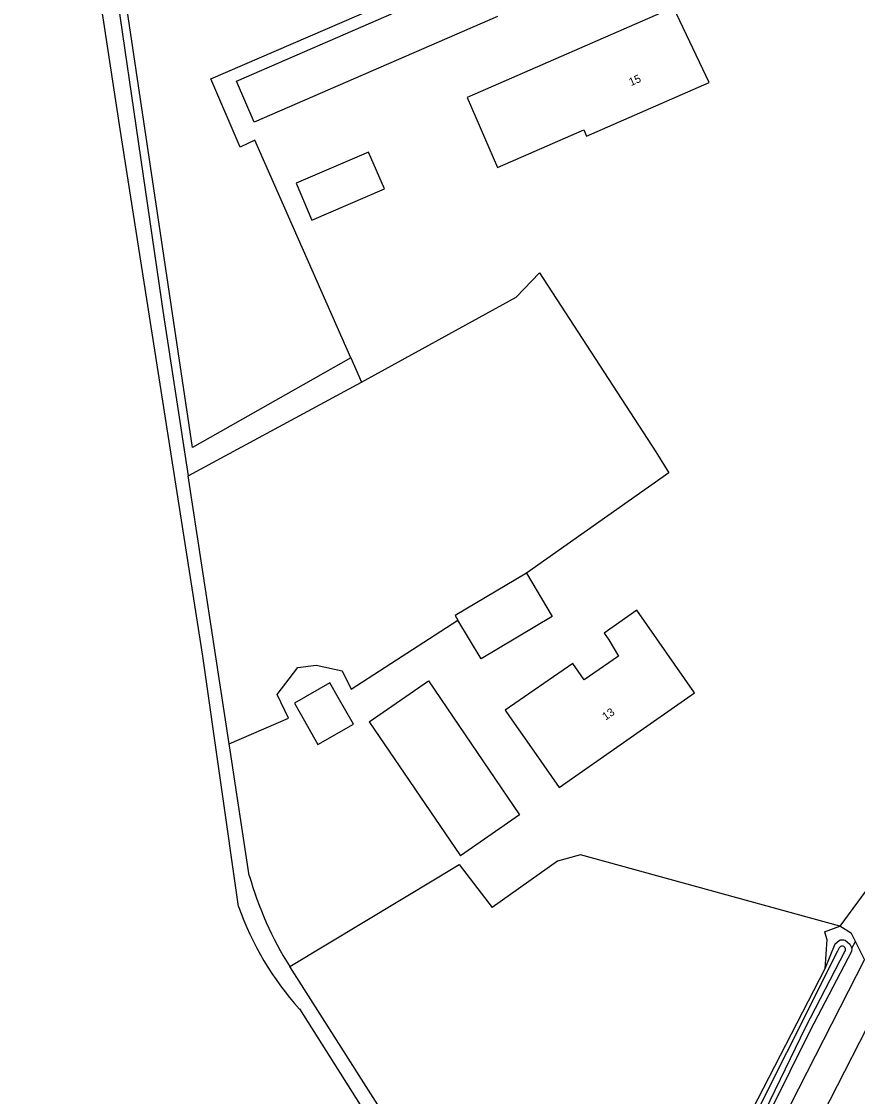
# Model space of a CAD drawing. Extents: x 141000 to 143000, y 400580 to 403500.
# Drawn here: x 141613.6 to 141718.1, y 403010.7 to 403145 of the extents above; entities that cross this region are included whole.
import ezdxf

# ---------------------------------------------------------------- set-up
doc = ezdxf.new("R2010")
doc.units = 0
for name, color, linetype in [('gg-afsc-draadraster', 7, 'Continuous'), ('gg-anno-huisnummerreeks BGT', 7, 'Continuous'), ('gg-bbg-bijgebouw', 7, 'Continuous'), ('gg-bbg-gedigitaliseerde bijgebouw', 7, 'Continuous'), ('gg-bbg-hoofdgebouw', 7, 'Continuous'), ('gg-bbg-luifel en loopbrug', 7, 'Continuous'), ('gg-knt-bronhoudergrens', 7, 'Continuous'), ('gg-knt-verharding', 7, 'Continuous'), ('gg-kntw-bovenkant insteek waterloop', 7, 'Continuous'), ('gg-kntw-waterlijn', 7, 'Continuous'), ('gt-grn-groengrens', 7, 'Continuous')]:
    doc.layers.add(name, color=color, linetype=linetype)

msp = doc.modelspace()

# ---------------------------------------------------------------- linework, layer by layer
at = {"layer": 'gg-afsc-draadraster'}
msp.add_line((141713.99, 403026.62), (141688.28, 402976.92), dxfattribs=at)
msp.add_lwpolyline([(141713.95, 403031.23), (141714.23, 403030.27), (141713.99, 403026.62)], dxfattribs=at)
at = {"layer": 'gg-bbg-bijgebouw'}
for points in [[(141673.08, 403145.62), (141642.64, 403132.39), (141640.43, 403137.54), (141670.57, 403150.63)], [(141676.67, 403076.07), (141667.78, 403070.76), (141668.12, 403070.2)], [(141676.67, 403076.07), (141679.9, 403070.66), (141671.01, 403065.36), (141668.12, 403070.2)], [(141653.16, 403060.51), (141652.12, 403062.35), (141647.68, 403059.83), (141648.39, 403058.56)], [(141648.39, 403058.56), (141650.6, 403054.66), (141655.05, 403057.18), (141653.16, 403060.51)]]:
    msp.add_lwpolyline(points, dxfattribs=at)
at = {"layer": 'gg-bbg-gedigitaliseerde bijgebouw'}
msp.add_line((141657.02, 403057.46), (141668.42, 403040.74), dxfattribs=at)
msp.add_lwpolyline([(141657.02, 403057.46), (141664.42, 403062.59), (141675.82, 403045.87), (141668.42, 403040.74)], dxfattribs=at)
at = {"layer": 'gg-bbg-hoofdgebouw'}
for points in [[(141673.07, 403126.74), (141683.85, 403131.43), (141684.18, 403130.66), (141699.52, 403137.35), (141695.07, 403146.73), (141669.27, 403135.48), (141673.07, 403126.74)], [(141682.49, 403064.75), (141674.03, 403058.95), (141674.57, 403058.15), (141677.89, 403053.39), (141680.75, 403049.29), (141697.69, 403061.09), (141690.49, 403071.43), (141686.39, 403068.57), (141686.98, 403067.73), (141688.2, 403065.67), (141683.89, 403062.71), (141682.49, 403064.75)]]:
    msp.add_lwpolyline(points, dxfattribs=at)
at = {"layer": 'gg-bbg-luifel en loopbrug'}
msp.add_lwpolyline([(141656.94, 403128.67), (141647.88, 403124.77), (141649.85, 403120.18), (141658.92, 403124.08), (141656.94, 403128.67)], dxfattribs=at)
at = {"layer": 'gg-knt-bronhoudergrens'}
for p in [(141654.73, 403102.94), (141634.38, 403088.22)]:
    msp.add_line(p, (141656.06, 403099.93), dxfattribs=at)
for points in [[(141654.73, 403102.94), (141634.94, 403091.76), (141616.15, 403217.64), (141674.51, 403229.38)], [(141654.73, 403102.94), (141642.73, 403130.14), (141640.91, 403129.3), (141637.23, 403137.84), (141657.61, 403146.59), (141653.62, 403158.13), (141633.01, 403151.17), (141629.1, 403162.73), (141655.24, 403172.36), (141659.18, 403161.13), (141690.34, 403171.52), (141691.99, 403172.11), (141691.61, 403174.34), (141694.24, 403175.31), (141686.11, 403197.59), (141674.51, 403229.38)], [(141656.06, 403099.93), (141675.4, 403110.56), (141678.33, 403113.59), (141692.84, 403091.22), (141694.48, 403088.58), (141676.67, 403076.07)], [(141639.52, 403054.71), (141646.93, 403057.93), (141645.53, 403060.9), (141648.11, 403064.26), (141650.39, 403064.56), (141653.63, 403063.84), (141654.79, 403061.56), (141668.12, 403070.2)], [(141715.87, 403031.94), (141683.42, 403040.88), (141680.57, 403040.09), (141672.41, 403034.3)], [(141647.1, 403026.91), (141665.51, 403038), (141668.27, 403039.67), (141672.41, 403034.3)]]:
    msp.add_lwpolyline(points, dxfattribs=at)
at = {"layer": 'gg-knt-verharding'}
for p, q in [((141719.1, 403036.35), (141715.87, 403031.94)), ((141716.2, 403031.73), (141715.87, 403031.94)), ((141713.71, 403008.47), (141724.6, 403029.76)), ((141718.93, 403027.79), (141717.81, 403030.04)), ((141718.93, 403027.79), (141689.37, 402969.99))]:
    msp.add_line(p, q, dxfattribs=at)
msp.add_lwpolyline([(141717.81, 403030.04), (141717.72, 403030.21), (141717.31, 403031.05), (141716.2, 403031.73)], dxfattribs=at)
at = {"layer": 'gg-kntw-bovenkant insteek waterloop'}
for p, q in [((141639.52, 403054.71), (141634.38, 403088.22)), ((141715.21, 403029.72), (141713.99, 403026.62))]:
    msp.add_line(p, q, dxfattribs=at)
for points in [[(141640.68, 403034.41), (141636.21, 403065.69), (141625.9, 403131.54), (141617, 403189.96), (141613.56, 403216.44)], [(141620.52, 403181.61), (141622.42, 403169.14), (141631.3, 403108.29), (141634.38, 403088.22)], [(141642.04, 403038.29), (141639.64, 403053.95), (141639.52, 403054.71)], [(141717.37, 403029.19), (141717.31, 403028.8), (141712.14, 403018.92), (141704.49, 403003.47), (141696.46, 402988.14), (141690.84, 402976.65), (141690.51, 402976.04)], [(141715.21, 403029.72), (141715.55, 403030.01), (141715.9, 403030.23), (141716.33, 403030.25), (141716.52, 403030.19), (141717.11, 403029.7), (141717.37, 403029.19)], [(141684.09, 402969), (141663.63, 403000.93), (141647.1, 403026.91)], [(141648.3, 403021.6), (141683, 402966.71), (141683.3, 402966.34)]]:
    msp.add_lwpolyline(points, dxfattribs=at)
for centre, radius, start, end in [((141683.35, 403049.82), 42.89, 195.5906, 212.2868), ((141677.01, 403047.34), 38.56, 199.5926, 221.8841)]:
    msp.add_arc(centre, radius, start, end, dxfattribs=at)
at = {"layer": 'gg-kntw-waterlijn'}
for points in [[(141715.78, 403029.25), (141715.55, 403028.84), (141702.82, 403003.43), (141689.37, 402977.2)], [(141716.49, 403028.81), (141711.5, 403019.25), (141703.99, 403003.65), (141695.81, 402988.47), (141690.04, 402976.67)]]:
    msp.add_lwpolyline(points, dxfattribs=at)
msp.add_arc((141716.14, 403029.03), 0.42, 328.111, 148.4418, dxfattribs=at)
at = {"layer": 'gt-grn-groengrens'}
for p, q in [((141713.95, 403031.23), (141715.87, 403031.94)), ((141717.37, 403029.19), (141717.81, 403030.04))]:
    msp.add_line(p, q, dxfattribs=at)

# ---------------------------------------------------------------- texts
at = {"layer": 'gg-anno-huisnummerreeks BGT'}
for s, rotation, p in [('15', 23.6, (141689.74, 403136.9)), ('13', 34.9, (141686.58, 403057.62))]:
    msp.add_text(s, height=1, rotation=rotation, dxfattribs=at).set_placement(p)

doc.saveas('drawing.dxf')
